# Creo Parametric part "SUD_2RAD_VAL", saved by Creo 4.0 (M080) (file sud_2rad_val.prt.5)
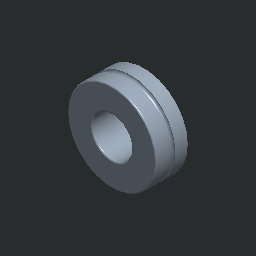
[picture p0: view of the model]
Units: millimeter Kilogram Sec (mmKs); MM, KILOGRAM, SECS
Materials in the file: OCEL_N

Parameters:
  MFG_WP_MATERIAL = "RO6_8"
  NAZOV = "SUD_2RAD_VAL"
  PTC_MATERIAL_NAME = "OCEL_N"

Other parameters: HMOTNOST, HUSTOTA, D26

Created from: SOUD_2RAD_VAL.PRT

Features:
  1. datum plane "DTM5"
  2. cut
  3. round

Layers: 1, 2, 3, 4, 5, 6, 7, 8, 9, 10, 11, 12, 13, 14, 15, 16, 17, 18, 19, 20, 21, 22, 23, 24, 25, 26, 27, 28, 29, 30, 31, 32

Family table entries: GENERIC, LOZISKO_22308J, SUD_2RAD_VAL, value(d_val), value(i_val), LOZISKO_22309J, SUD_2RAD_VAL, 2/Y, 2/B, LOZISKO_22310J, SUD_2RAD_VAL, !/I, 2/D, LOZISKO_22311J, SUD_2RAD_VAL, 2/^, LOZISKO_22312J, SUD_2RAD_VAL, !/N, 2/G, LOZISKO_22313M, SUD_2RAD_VAL, 2/H, LOZISKO_22214J, SUD_2RAD_VAL, 2/?, LOZISKO_22314J, SUD_2RAD_VAL, LOZISKO_22215J, SUD_2RAD_VAL, 2/?, LOZISKO_22315J, SUD_2RAD_VAL, 2/d, LOZISKO_22216J, SUD_2RAD_VAL, !/T, LOZISKO_22316J, SUD_2RAD_VAL, !/T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

Surfaces: 10 torus, 2 plane, 2 cylinder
